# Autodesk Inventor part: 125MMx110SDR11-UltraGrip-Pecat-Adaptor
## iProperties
Created: 2012-05
Part Number: 125MMx110SDR11-UltraGrip-Pecat-Adaptor
Document SubType Name: Modeling
Designer: D Cole
Density: 1 g/cm^3
Author: D Cole
